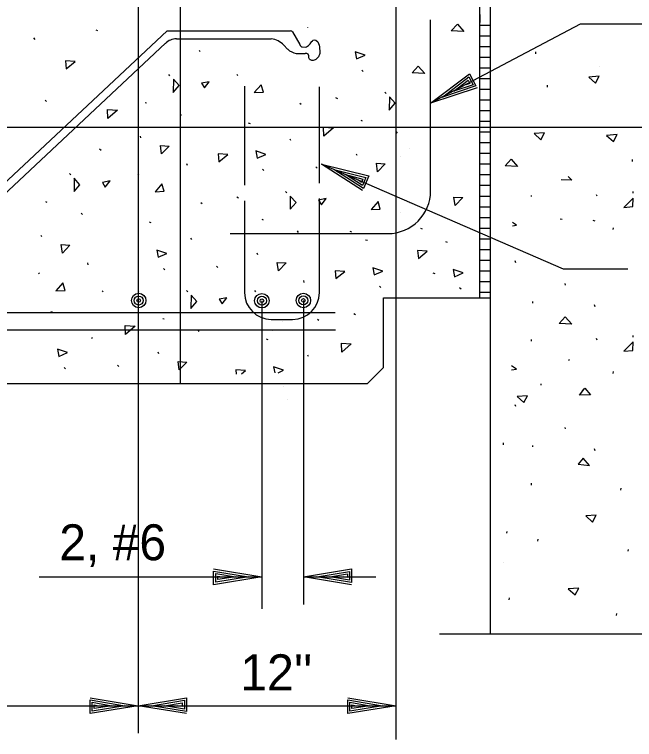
# Model space of a CAD drawing. Extents: x 22369.6 to 22428.3, y 22369.6 to 22415.
# Drawn here: x 22409.492 to 22412.698, y 22375.812 to 22379.562 of the extents above; entities that cross this region are included whole.
import ezdxf

# ---------------------------------------------------------------- set-up
doc = ezdxf.new("R2010")
doc.units = 0
for name, color, linetype in [('Level 1', 7, 'Continuous'), ('Level 10', 7, 'Continuous'), ('Level 2', 7, 'Continuous'), ('Level 4', 7, 'Continuous'), ('Level 7', 7, 'Continuous'), ('Level 8', 7, 'Continuous')]:
    doc.layers.add(name, color=color, linetype=linetype)

msp = doc.modelspace()

# ---------------------------------------------------------------- linework, layer by layer
at = {"layer": 'Level 1'}
for p, q in [((22411.465, 22375.8119), (22411.465, 22381.4376)), ((22410.1316, 22380.1105), (22410.1316, 22375.8452)), ((22412.5163, 22379.2934), (22412.5163, 22379.2934)), ((22410.1743, 22379.103), (22410.1672, 22379.106)), ((22411.6438, 22379.1028), (22411.6438, 22379.1028)), ((22411.705, 22379.1352), (22411.705, 22379.1352)), ((22410.3558, 22379.0396), (22410.3501, 22379.0475)), ((22405.5525, 22378.9803), (22411.9528, 22378.9803)), ((22411.4732, 22378.9479), (22411.4674, 22378.9557)), ((22411.9528, 22378.9803), (22414.1995, 22378.9803)), ((22411.5348, 22378.8705), (22411.5348, 22378.8705)), ((22411.489, 22378.8264), (22411.489, 22378.8264)), ((22411.0566, 22378.7666), (22411.0496, 22378.7736)), ((22411.0789, 22378.7884), (22411.0789, 22378.7884)), ((22411.1425, 22378.7608), (22411.1425, 22378.7608)), ((22412.1655, 22378.6202), (22412.1655, 22378.626)), ((22412.5047, 22378.6229), (22412.5018, 22378.63)), ((22412.6912, 22378.6375), (22412.6912, 22378.6468)), ((22411.5357, 22378.5831), (22411.5357, 22378.5831)), ((22411.4899, 22378.539), (22411.4899, 22378.539)), ((22411.3166, 22378.3927), (22411.3072, 22378.3957)), ((22409.9512, 22378.1282), (22409.945, 22378.1335)), ((22410.1401, 22378.1314), (22410.1401, 22378.1314)), ((22410.0943, 22378.0873), (22410.0943, 22378.0873)), ((22410.771, 22378.0816), (22410.771, 22376.4881)), ((22410.9857, 22378.083), (22410.9857, 22376.5103)), ((22410.8794, 22377.9726), (22410.8794, 22377.9726)), ((22410.8281, 22377.926), (22410.8281, 22377.926)), ((22410.8038, 22377.8799), (22410.7944, 22377.8829)), ((22410.884, 22377.6372), (22410.884, 22377.6372)), ((22410.9056, 22377.5717), (22410.9056, 22377.5717)), ((22412.0381, 22376.8787), (22412.0396, 22376.8884)), ((22411.9528, 22376.7279), (22411.9528, 22376.7279)), ((22412.0217, 22376.7279), (22412.0217, 22376.7279)), ((22409.6201, 22376.6536), (22410.771, 22376.6536)), ((22410.7017, 22376.6536), (22410.7017, 22376.6536)), ((22410.771, 22376.6536), (22410.771, 22376.6536)), ((22410.9857, 22376.6536), (22411.3602, 22376.6536)), ((22410.9857, 22376.6536), (22410.9857, 22376.6536)), ((22411.055, 22376.6536), (22411.055, 22376.6536)), ((22411.689, 22376.3578), (22413.4027, 22376.3578)), ((22406.3621, 22375.9869), (22410.1316, 22375.9869)), ((22410.0623, 22375.9869), (22410.0623, 22375.9869)), ((22410.1316, 22375.9869), (22411.465, 22375.9869)), ((22410.1316, 22375.9869), (22410.1316, 22375.9869)), ((22410.1316, 22375.9869), (22410.1316, 22375.9869)), ((22410.201, 22375.9869), (22410.201, 22375.9869)), ((22411.3956, 22375.9869), (22411.3956, 22375.9869)), ((22411.465, 22375.9869), (22411.465, 22375.9869))]:
    msp.add_line(p, q, dxfattribs=at)
for points in [[(22412.7409, 22379.5119), (22412.4165, 22379.5119), (22411.6438, 22379.1028)], [(22411.8835, 22379.1829), (22411.6438, 22379.1028), (22411.8448, 22379.256), (22411.8778, 22379.1935), (22411.705, 22379.1352), (22411.8416, 22379.2392), (22411.8628, 22379.1991), (22411.764, 22379.1664), (22411.8384, 22379.2224), (22411.8471, 22379.2059), (22411.8252, 22379.1989)], [(22412.6632, 22378.2452), (22412.3308, 22378.2452), (22411.0789, 22378.7884)], [(22411.2912, 22378.6512), (22411.0789, 22378.7884), (22411.3241, 22378.727), (22411.296, 22378.6622), (22411.1425, 22378.7608), (22411.309, 22378.7191), (22411.291, 22378.6775), (22411.2037, 22378.7342), (22411.2939, 22378.7111), (22411.2865, 22378.6939), (22411.2673, 22378.7066)], [(22412.0879, 22378.4723), (22412.0671, 22378.4863)], [(22412.0879, 22377.7279), (22412.0621, 22377.7452)], [(22410.5217, 22376.6949), (22410.771, 22376.6536), (22410.5217, 22376.6123), (22410.5217, 22376.6829), (22410.7017, 22376.6536), (22410.5324, 22376.6256), (22410.5324, 22376.6709), (22410.635, 22376.6536), (22410.543, 22376.6389), (22410.543, 22376.6576), (22410.5657, 22376.6536)], [(22411.235, 22376.6123), (22410.9857, 22376.6536), (22411.235, 22376.6949), (22411.235, 22376.6243), (22411.055, 22376.6536), (22411.2244, 22376.6816), (22411.2244, 22376.6363), (22411.1217, 22376.6536), (22411.2137, 22376.6683), (22411.2137, 22376.6496), (22411.191, 22376.6536)], [(22409.8823, 22376.0283), (22410.1316, 22375.9869), (22409.8823, 22375.9456), (22409.8823, 22376.0163), (22410.0623, 22375.9869), (22409.893, 22375.9589), (22409.893, 22376.0043), (22409.9956, 22375.9869), (22409.9036, 22375.9723), (22409.9036, 22375.9909), (22409.9263, 22375.9869)], [(22410.381, 22375.9456), (22410.1316, 22375.9869), (22410.381, 22376.0283), (22410.381, 22375.9576), (22410.201, 22375.9869), (22410.3703, 22376.0149), (22410.3703, 22375.9696), (22410.2676, 22375.9869), (22410.3596, 22376.0016), (22410.3596, 22375.9829), (22410.337, 22375.9869)], [(22411.2156, 22376.0283), (22411.465, 22375.9869), (22411.2156, 22375.9456), (22411.2156, 22376.0163), (22411.3956, 22375.9869), (22411.2263, 22375.9589), (22411.2263, 22376.0043), (22411.329, 22375.9869), (22411.237, 22375.9723), (22411.237, 22375.9909), (22411.2596, 22375.9869)]]:
    msp.add_lwpolyline(points, dxfattribs=at)
msp.add_lwpolyline([(22411.0786, 22378.5779), (22411.1034, 22378.61), (22411.0634, 22378.6022)], close=True, dxfattribs=at)
at = {"layer": 'Level 10'}
for p, q in [((22411.9528, 22376.3578), (22411.9528, 22379.9265)), ((22411.6438, 22378.6506), (22411.6438, 22379.5353)), ((22410.6814, 22379.1919), (22410.6814, 22378.6803)), ((22411.0683, 22378.689), (22411.0683, 22379.1876)), ((22410.6814, 22378.5986), (22410.6814, 22378.1235)), ((22411.0683, 22378.1235), (22411.0683, 22378.6103)), ((22410.6067, 22378.429), (22411.4222, 22378.429)), ((22411.4, 22378.0958), (22411.9528, 22378.0958)), ((22411.4, 22377.7365), (22411.4, 22378.0958)), ((22408.3785, 22378.0214), (22411.15, 22378.0214)), ((22410.8196, 22377.9853), (22410.9301, 22377.9853)), ((22406.3621, 22377.9313), (22411.1526, 22377.9313)), ((22411.3171, 22377.6536), (22411.4, 22377.7365)), ((22406.3621, 22377.6536), (22411.3171, 22377.6536))]:
    msp.add_line(p, q, dxfattribs=at)
for centre, radius, start, end in [((22411.4222, 22378.6506), 0.2215, 270, 0), ((22410.8196, 22378.1235), 0.1382, 180, 270), ((22410.9301, 22378.1235), 0.1382, 270, 360)]:
    msp.add_arc(centre, radius, start, end, dxfattribs=at)
at = {"layer": 'Level 2'}
for p, q in [((22410.3497, 22377.6536), (22410.3497, 22380.2357)), ((22411.8975, 22379.5616), (22411.8975, 22379.5201)), ((22409.2862, 22378.5463), (22410.2807, 22379.4778)), ((22410.2807, 22379.4778), (22410.919, 22379.4778)), ((22411.0067, 22379.4961), (22411.0067, 22379.4957)), ((22410.9292, 22379.4718), (22410.9673, 22379.4071)), ((22409.279, 22378.4828), (22410.2735, 22379.4142)), ((22410.3298, 22379.4363), (22410.8198, 22379.4363)), ((22410.8843, 22379.4041), (22410.9043, 22379.3826)), ((22410.9486, 22379.3597), (22410.9952, 22379.3599))]:
    msp.add_line(p, q, dxfattribs=at)
msp.add_lwpolyline([(22410.9673, 22379.4071), (22410.9692, 22379.4022), (22410.9687, 22379.4022), (22410.9756, 22379.3954), (22410.9791, 22379.3944), (22410.9946, 22379.3939), (22411.0022, 22379.3952), (22411.0115, 22379.4012), (22411.0207, 22379.4108), (22411.0237, 22379.4163), (22411.0251, 22379.4174), (22411.0259, 22379.4202), (22411.032, 22379.4261), (22411.0365, 22379.4289), (22411.0436, 22379.4314), (22411.0508, 22379.4292), (22411.0607, 22379.4217), (22411.0637, 22379.4129), (22411.067, 22379.4033), (22411.069, 22379.3957), (22411.0713, 22379.3658), (22411.0708, 22379.3662), (22411.07, 22379.3604), (22411.0683, 22379.3562), (22411.066, 22379.3483), (22411.0632, 22379.3436), (22411.0576, 22379.3358), (22411.0499, 22379.33), (22411.0458, 22379.3276), (22411.0365, 22379.3244), (22411.0353, 22379.3247), (22411.0348, 22379.3241), (22411.031, 22379.3247), (22411.0287, 22379.3246), (22411.0222, 22379.3271), (22411.0201, 22379.3276), (22411.0201, 22379.3284), (22411.0168, 22379.3317), (22411.0143, 22379.338), (22411.0136, 22379.3471), (22411.0134, 22379.3493), (22411.0103, 22379.3564), (22411.0032, 22379.3601), (22411.0028, 22379.3592), (22411.0028, 22379.3597), (22410.9952, 22379.3599)], dxfattribs=at)
for centre, radius in [((22410.1341, 22378.0828), 0.0373), ((22410.1341, 22378.0828), 0.0233), ((22410.1341, 22378.0828), 0.00933), ((22410.771, 22378.0816), 0.0373), ((22410.771, 22378.0816), 0.0233), ((22410.771, 22378.0816), 0.00933), ((22410.9857, 22378.083), 0.0373), ((22410.9857, 22378.083), 0.0233), ((22410.9857, 22378.083), 0.00933)]:
    msp.add_circle(centre, radius, dxfattribs=at)
for centre, radius, start, end in [((22410.9178, 22379.464), 0.0139, 34.4776, 84.9264), ((22410.3298, 22379.3534), 0.0829, 90, 134.0411), ((22410.3298, 22379.3534), 0.0829, 132.7844, 133.4737), ((22410.8096, 22379.3349), 0.1019, 42.8324, 84.2307), ((22410.9786, 22379.4718), 0.116, 230.268, 255.0673)]:
    msp.add_arc(centre, radius, start, end, dxfattribs=at)
at = {"layer": 'Level 7'}
msp.add_line((22411.8975, 22378.0958), (22411.8975, 22381.6336), dxfattribs=at)
at = {"layer": 'Level 8'}
for p, q in [((22409.9233, 22379.4779), (22409.9139, 22379.481)), ((22411.8975, 22379.5077), (22411.9528, 22379.5077)), ((22409.5981, 22379.4338), (22409.5911, 22379.4408)), ((22411.8975, 22379.4525), (22411.9528, 22379.4525)), ((22410.4521, 22379.3711), (22410.4471, 22379.3761)), ((22411.8975, 22379.3972), (22411.9528, 22379.3972)), ((22412.1881, 22379.3596), (22412.1881, 22379.3696)), ((22411.8975, 22379.3419), (22411.9528, 22379.3419)), ((22410.2959, 22379.2452), (22410.2893, 22379.2518)), ((22410.6473, 22379.2456), (22410.6426, 22379.2512)), ((22411.2941, 22379.2677), (22411.2871, 22379.2747)), ((22411.8975, 22379.2866), (22411.9528, 22379.2866)), ((22411.8975, 22379.2314), (22411.9528, 22379.2314)), ((22411.8975, 22379.1761), (22411.9528, 22379.1761)), ((22412.2484, 22379.1863), (22412.2484, 22379.1962)), ((22411.4132, 22379.1534), (22411.4067, 22379.16)), ((22409.6566, 22379.1119), (22409.6496, 22379.119)), ((22410.9743, 22379.0961), (22410.9681, 22379.1014)), ((22411.1632, 22379.1255), (22411.1542, 22379.1306)), ((22411.8975, 22379.1208), (22411.9528, 22379.1208)), ((22411.8975, 22379.0655), (22411.9528, 22379.0655)), ((22410.712, 22378.9972), (22410.7026, 22379.0003)), ((22411.2916, 22379.0112), (22411.2846, 22379.0142)), ((22411.8975, 22379.0102), (22411.9528, 22379.0102)), ((22411.8975, 22378.955), (22411.9528, 22378.955)), ((22410.1458, 22378.9241), (22410.1429, 22378.9322)), ((22410.9208, 22378.9111), (22410.9165, 22378.9173)), ((22411.8975, 22378.8997), (22411.9528, 22378.8997)), ((22409.9393, 22378.8584), (22409.9322, 22378.8654)), ((22411.2631, 22378.8324), (22411.2602, 22378.8405)), ((22411.8975, 22378.8444), (22411.9528, 22378.8444)), ((22412.6877, 22378.8025), (22412.6877, 22378.8124)), ((22410.3859, 22378.7809), (22410.3836, 22378.7903)), ((22411.8975, 22378.7891), (22411.9528, 22378.7891)), ((22409.7831, 22378.7324), (22409.7765, 22378.739)), ((22410.1345, 22378.7328), (22410.1298, 22378.7384)), ((22410.7813, 22378.7549), (22410.7743, 22378.7619)), ((22411.8975, 22378.7339), (22411.9528, 22378.7339)), ((22411.8975, 22378.6786), (22411.9528, 22378.6786)), ((22410.6504, 22378.6127), (22410.6414, 22378.6178)), ((22410.9005, 22378.6406), (22410.8939, 22378.6472)), ((22411.8975, 22378.6233), (22411.9528, 22378.6233)), ((22409.6615, 22378.5902), (22409.6544, 22378.5932)), ((22410.4615, 22378.5833), (22410.4553, 22378.5886)), ((22411.8975, 22378.568), (22411.9528, 22378.568)), ((22409.843, 22378.5269), (22409.8373, 22378.5347)), ((22410.7788, 22378.4984), (22410.7718, 22378.5015)), ((22411.8975, 22378.5127), (22411.9528, 22378.5127)), ((22412.3234, 22378.5011), (22412.3141, 22378.5042)), ((22410.1992, 22378.4845), (22410.1898, 22378.4875)), ((22412.4937, 22378.493), (22412.4844, 22378.496)), ((22410.9604, 22378.4351), (22410.9546, 22378.4429)), ((22411.2369, 22378.4362), (22411.2275, 22378.4392)), ((22411.6018, 22378.4524), (22411.5924, 22378.4555)), ((22411.8975, 22378.4575), (22411.9528, 22378.4575)), ((22412.5882, 22378.4497), (22412.5897, 22378.4594)), ((22409.633, 22378.4114), (22409.6301, 22378.4194)), ((22410.4081, 22378.3983), (22410.4037, 22378.4045)), ((22411.8975, 22378.4022), (22411.9528, 22378.4022)), ((22411.7315, 22378.3835), (22411.7221, 22378.3865)), ((22410.7504, 22378.3196), (22410.7474, 22378.3277)), ((22411.8975, 22378.3469), (22411.9528, 22378.3469)), ((22409.8731, 22378.2681), (22409.8708, 22378.2775)), ((22411.8975, 22378.2916), (22411.9528, 22378.2916)), ((22412.0849, 22378.2784), (22412.0805, 22378.2872)), ((22410.2685, 22378.2421), (22410.2615, 22378.2491)), ((22410.5438, 22378.2538), (22410.5368, 22378.2609)), ((22409.6217, 22378.22), (22409.617, 22378.2256)), ((22411.6667, 22378.2212), (22411.6573, 22378.2242)), ((22411.8975, 22378.2364), (22411.9528, 22378.2364)), ((22410.9905, 22378.1763), (22410.9881, 22378.1857)), ((22411.8975, 22378.1811), (22411.9528, 22378.1811)), ((22412.3403, 22378.1629), (22412.3397, 22378.171)), ((22410.3877, 22378.1279), (22410.3811, 22378.1344)), ((22410.7391, 22378.1282), (22410.7344, 22378.1338)), ((22411.3859, 22378.1503), (22411.3788, 22378.1573)), ((22411.8008, 22378.1411), (22411.7938, 22378.1481)), ((22411.8975, 22378.1258), (22411.9528, 22378.1258)), ((22412.1717, 22378.0698), (22412.173, 22378.0773)), ((22412.4947, 22378.0501), (22412.4919, 22378.06)), ((22409.6889, 22378.0218), (22409.6796, 22378.0249)), ((22411.255, 22378.0082), (22411.246, 22378.0132)), ((22410.266, 22377.9856), (22410.259, 22377.9887)), ((22411.0661, 22377.9787), (22411.0584, 22377.9853)), ((22410.4476, 22377.9223), (22410.4418, 22377.9302)), ((22412.6912, 22377.8931), (22412.6912, 22377.9023)), ((22409.8953, 22377.8855), (22409.8909, 22377.8917)), ((22412.1655, 22377.8717), (22412.1655, 22377.8816)), ((22412.5047, 22377.8784), (22412.5018, 22377.8856)), ((22410.2376, 22377.8068), (22410.2346, 22377.8149)), ((22411.0126, 22377.7937), (22411.0083, 22377.7999)), ((22412.3581, 22377.7722), (22412.3617, 22377.7799)), ((22409.7557, 22377.7293), (22409.7487, 22377.7363)), ((22410.0311, 22377.741), (22410.024, 22377.7481)), ((22412.5882, 22377.7053), (22412.5897, 22377.7149)), ((22412.2148, 22377.6448), (22412.2154, 22377.6521)), ((22412.4265, 22377.6116), (22412.4315, 22377.6199)), ((22412.0849, 22377.534), (22412.0805, 22377.5428)), ((22412.3403, 22377.4184), (22412.3397, 22377.4266)), ((22412.0198, 22377.3369), (22412.0213, 22377.3466)), ((22412.1717, 22377.3254), (22412.173, 22377.3329)), ((22412.4947, 22377.3057), (22412.4919, 22377.3156)), ((22412.1655, 22377.1272), (22412.1655, 22377.1372)), ((22412.628, 22377.1024), (22412.6295, 22377.112)), ((22412.1987, 22376.8386), (22412.2002, 22376.8482)), ((22412.6657, 22376.7858), (22412.6672, 22376.7955)), ((22412.0503, 22376.5343), (22412.0518, 22376.5439)), ((22412.6054, 22376.4542), (22412.6069, 22376.4638))]:
    msp.add_line(p, q, dxfattribs=at)
for points in [[(22411.7504, 22379.4781), (22411.782, 22379.5122), (22411.8158, 22379.4744)], [(22411.2601, 22379.3322), (22411.3045, 22379.3517), (22411.2531, 22379.3694)], [(22409.8061, 22379.3186), (22409.7562, 22379.3221), (22409.7597, 22379.2813)], [(22411.548, 22379.2601), (22411.5795, 22379.2942), (22411.6133, 22379.2564)], [(22410.343, 22379.1946), (22410.3135, 22379.2276), (22410.3126, 22379.159)], [(22410.474, 22379.1825), (22410.4989, 22379.2146), (22410.4589, 22379.2068)], [(22412.4611, 22379.2389), (22412.4964, 22379.2074), (22412.5153, 22379.2427)], [(22410.7314, 22379.158), (22410.7786, 22379.1607), (22410.767, 22379.1991)], [(22411.4604, 22379.1028), (22411.4308, 22379.1359), (22411.43, 22379.0672)], [(22409.9748, 22379.0241), (22409.9729, 22379.0705), (22410.0236, 22379.0677)], [(22411.0922, 22378.9323), (22411.0903, 22378.9787), (22411.1409, 22378.9759)], [(22412.1787, 22378.9463), (22412.214, 22378.9148), (22412.2329, 22378.9502)], [(22412.5537, 22378.9371), (22412.589, 22378.9056), (22412.6079, 22378.9409)], [(22410.2524, 22378.8408), (22410.2463, 22378.8846), (22410.2916, 22378.8818)], [(22410.5949, 22378.8379), (22410.5449, 22378.8414), (22410.5484, 22378.8006)], [(22410.7473, 22378.8194), (22410.7917, 22378.8389), (22410.7403, 22378.8566)], [(22412.0283, 22378.7798), (22412.0598, 22378.814), (22412.0936, 22378.7761)], [(22411.3697, 22378.749), (22411.3636, 22378.7929), (22411.4089, 22378.7901)], [(22409.8302, 22378.6818), (22409.8007, 22378.7148), (22409.7999, 22378.6462)], [(22409.9612, 22378.6697), (22409.9861, 22378.7018), (22409.9461, 22378.694)], [(22410.2186, 22378.6452), (22410.2658, 22378.6479), (22410.2542, 22378.6863)], [(22410.9476, 22378.59), (22410.918, 22378.6231), (22410.9172, 22378.5545)], [(22411.7706, 22378.5738), (22411.7645, 22378.6177), (22411.8097, 22378.6149)], [(22411.3359, 22378.5534), (22411.3832, 22378.5561), (22411.3716, 22378.5945)], [(22412.6887, 22378.5683), (22412.6912, 22378.6126), (22412.6421, 22378.5647)], [(22409.7396, 22378.328), (22409.7335, 22378.3718), (22409.7787, 22378.369)], [(22410.2345, 22378.3066), (22410.279, 22378.3261), (22410.2275, 22378.3439)], [(22411.6265, 22378.3377), (22411.5766, 22378.3412), (22411.5801, 22378.3004)], [(22410.8569, 22378.2362), (22410.8508, 22378.2801), (22410.8961, 22378.2773)], [(22411.3519, 22378.2148), (22411.3963, 22378.2344), (22411.3448, 22378.2521)], [(22411.7668, 22378.2056), (22411.8112, 22378.2252), (22411.7598, 22378.2429)], [(22411.1994, 22378.2333), (22411.1495, 22378.2368), (22411.153, 22378.196)], [(22409.7058, 22378.1324), (22409.753, 22378.1351), (22409.7414, 22378.1735)], [(22410.4348, 22378.0772), (22410.4052, 22378.1103), (22410.4044, 22378.0417)], [(22410.5658, 22378.0651), (22410.5906, 22378.0973), (22410.5506, 22378.0894)], [(22412.3078, 22377.9637), (22412.3393, 22377.9979), (22412.3732, 22377.9601)], [(22410.0666, 22377.9067), (22410.0647, 22377.9531), (22410.1154, 22377.9503)], [(22412.6887, 22377.8239), (22412.6912, 22377.8682), (22412.6421, 22377.8202)], [(22409.7217, 22377.7938), (22409.7662, 22377.8134), (22409.7147, 22377.8311)], [(22411.1839, 22377.8149), (22411.1821, 22377.8614), (22411.2327, 22377.8586)], [(22410.3442, 22377.7234), (22410.338, 22377.7673), (22410.3833, 22377.7645)], [(22412.4142, 22377.5936), (22412.4409, 22377.6289), (22412.4709, 22377.5949)], [(22412.0903, 22377.5866), (22412.1256, 22377.5551), (22412.1445, 22377.5904)], [(22412.4651, 22377.2292), (22412.4323, 22377.2671), (22412.4059, 22377.2357)], [(22412.4454, 22376.9684), (22412.4807, 22376.9369), (22412.4996, 22376.9723)], [(22412.355, 22376.5916), (22412.3903, 22376.5601), (22412.4092, 22376.5954)]]:
    msp.add_lwpolyline(points, close=True, dxfattribs=at)
for points in [[(22412.3732, 22378.7045), (22412.3189, 22378.7075)], [(22412.3549, 22378.7249), (22412.3732, 22378.7045)], [(22412.067, 22378.4696), (22412.0879, 22378.4723)], [(22410.6866, 22377.7205), (22410.6367, 22377.724), (22410.6386, 22377.7023)], [(22410.6649, 22377.7031), (22410.6866, 22377.7205)], [(22410.8545, 22377.7088), (22410.8835, 22377.7216), (22410.832, 22377.7393), (22410.8379, 22377.7083)], [(22412.062, 22377.7246), (22412.0879, 22377.7279)]]:
    msp.add_lwpolyline(points, dxfattribs=at)

# ---------------------------------------------------------------- texts
at = {"layer": 'Level 4'}
for s, height, p in [('2, #6', 0.18574, (22409.7233, 22376.7392)), ("12''", 0.18667, (22410.659, 22376.0658))]:
    msp.add_text(s, height=height, dxfattribs=at).set_placement(p)

doc.saveas('drawing.dxf')
